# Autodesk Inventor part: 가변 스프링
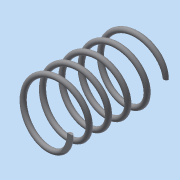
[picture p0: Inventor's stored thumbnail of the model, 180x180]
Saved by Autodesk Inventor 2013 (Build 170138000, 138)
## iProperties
Created: 2015-10
Part Number: 가변 스프링
Material: 강철, 연강
Document SubType Name: Modeling
Designer: Administrator
Density: 1 g/cm^3
Author: Administrator
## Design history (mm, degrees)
sketch "스케치1"
  geometry: L1 (0, 0)-(0, 18.948); L2 (0, 0)-(5.5, 0); L3 (0, 18.948)-(5.5, 18.948); C1 r 0.5 at (5.5, 0)
  constraints: 6 end point, 1 centre point, 1 horizontal alignment, 1 parallel, 1 perpendicular, 1 vertical
  dimensions: "d0" = 18.94782 distance of L1.start L1.end (derived); "d1" = 1 diameter of C1; "d2" = 11 diameter of L2.end L1
feature "코일1" sketch "스케치1" pitch "d3" = 10; turns "d5" = 5; dims "d4" = 18.94782 (= d0), "d6" = 0, angle "d7" = 90 deg, angle "d8" = 90 deg, "d9" = 0, "d10" = 0
sketch "스케치2"
  geometry: L1 (0, 6.5)-(18.948, 6.5); L2 (18.948, 6.5)-(18.948, -6.5); L3 (18.948, -6.5)-(0, -6.5); L4 (0, -6.5)-(0, 6.5); 2 further points
  constraints: 8 end point, 2 parallel, 1 coincident, 1 horizontal, 1 midpoint, 1 perpendicular
  dimensions: "d11" = 18.94782 distance of L2.end L3.end (derived); "d13" = 13 distance of L1.end L2.end
extrude "돌출1" sketch "스케치2" stored distance "d14" = 0; taper "d15" = 0 deg
node "솔리드1"
